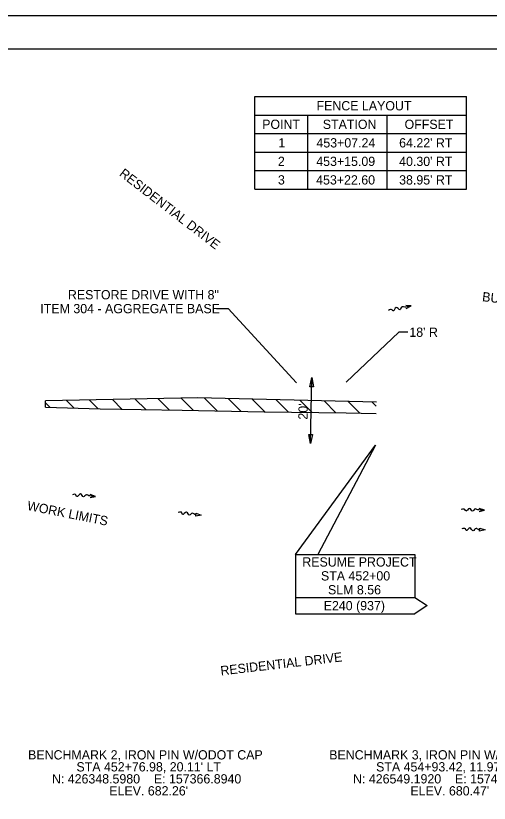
# Model space of a CAD drawing. Extents: x 0 to 3369, y -440 to 440.
# Drawn here: x 196.9 to 340, y 202 to 440 of the extents above; entities that cross this region are included whole.
import ezdxf

# ---------------------------------------------------------------- set-up
doc = ezdxf.new("R2010")
doc.units = 0
for name, color, linetype in [('_CIVIL_CONSTRUCTION', 7, 'Continuous'), ('GE_P_Alignment_100_Distances', 7, 'Continuous'), ('MT_P_PCB', 7, 'Continuous'), ('MT_P_Work_Area', 7, 'Continuous'), ('PF_X_Ground_Line', 7, 'Continuous'), ('PV_P_EOP', 7, 'Continuous'), ('PV_P_Shoulder', 7, 'Continuous'), ('SC_Scratch1', 7, 'Continuous')]:
    doc.layers.add(name, color=color, linetype=linetype)

msp = doc.modelspace()

# ---------------------------------------------------------------- linework, layer by layer
at = {"layer": '_CIVIL_CONSTRUCTION'}
for points in [[(286.92, 327.87), (285.8, 327.9), (286.42, 330.69)], [(285.46, 313.5), (286.58, 313.48), (285.95, 310.69)]]:
    msp.add_lwpolyline(points, close=True, dxfattribs=at)
at = {"layer": 'GE_P_Alignment_100_Distances'}
for p, q in [((251.92, 324.5), (205.89, 323.59)), ((212.23, 323.72), (214.47, 321.47)), ((219.16, 323.85), (221.74, 321.27)), ((226.1, 323.99), (228.96, 321.12)), ((233.03, 324.13), (236.18, 320.98)), ((239.96, 324.26), (243.39, 320.84)), ((246.9, 324.4), (250.6, 320.7)), ((305.91, 323.22), (251.92, 324.5)), ((253.92, 324.45), (257.78, 320.59)), ((261.16, 324.28), (264.97, 320.47)), ((268.4, 324.11), (272.16, 320.35)), ((275.65, 323.94), (279.34, 320.25)), ((282.89, 323.77), (286.51, 320.15)), ((205.84, 321.71), (205.89, 323.59)), ((205.87, 323), (207.2, 321.67)), ((290.13, 323.6), (293.68, 320.04)), ((297.37, 323.42), (300.9, 319.9)), ((304.62, 323.25), (305.88, 321.99))]:
    msp.add_line(p, q, dxfattribs=at)
msp.add_lwpolyline([(205.84, 321.71), (222.36, 321.26), (247.15, 320.76), (272.03, 320.35), (296.81, 320), (305.82, 319.78)], dxfattribs=at)
at = {"layer": 'MT_P_Work_Area'}
for p, q in [((316.44, 352.3), (314.78, 352.41)), ((314.95, 351.57), (316.44, 352.3)), ((220.98, 294.77), (219.41, 295.32)), ((219.35, 294.46), (220.98, 294.77)), ((336.99, 290.22), (338.6, 290.61)), ((338.6, 290.61), (337.01, 291.08))]:
    msp.add_line(p, q, dxfattribs=at)
for points in [[(316.44, 352.3), (314.8, 351.98), (314.13, 352), (313.69, 352.07), (313, 351.18), (311.89, 351.8), (310.95, 350.78), (310.64, 351.17), (309.57, 350.95)], [(220.98, 294.77), (219.32, 294.9), (218.68, 295.09), (218.27, 295.27), (217.37, 294.59), (216.46, 295.49), (215.29, 294.74), (215.09, 295.21), (214, 295.27)], [(338.6, 290.61), (336.94, 290.66), (336.29, 290.82), (335.87, 290.98), (335.01, 290.26), (334.06, 291.11), (332.92, 290.31), (332.7, 290.76), (331.6, 290.78)]]:
    msp.add_spline(points, degree=3, dxfattribs=at)
at = {"layer": 'PF_X_Ground_Line'}
msp.add_lwpolyline([(30, 430), (670, 430), (670, 10), (30, 10)], close=True, dxfattribs=at)
at = {"layer": 'PV_P_EOP'}
for p, q in [((269.18, 415.6), (333.18, 415.6)), ((269.18, 387.6), (269.18, 415.6)), ((333.18, 387.6), (333.18, 415.6)), ((269.18, 410), (333.18, 410)), ((285.18, 387.6), (285.18, 410)), ((309.18, 387.6), (309.18, 410)), ((269.18, 404.4), (333.18, 404.4)), ((269.18, 398.8), (333.18, 398.8)), ((269.18, 393.2), (333.18, 393.2)), ((269.18, 387.6), (333.18, 387.6)), ((257.6, 351.5), (261.06, 351.5)), ((261.06, 351.5), (281.73, 329.1)), ((312.73, 344.37), (296.82, 329.23)), ((315.42, 344.37), (312.73, 344.37)), ((285.95, 310.69), (286.42, 330.69)), ((281.51, 277.24), (281.51, 259.24)), ((281.51, 277.24), (317.51, 277.24)), ((317.51, 277.24), (317.51, 264.24)), ((281.51, 264.24), (317.51, 264.24)), ((281.51, 259.24), (317.51, 259.24))]:
    msp.add_line(p, q, dxfattribs=at)
for points in [[(281.51, 277.24), (305.6, 310.23), (288.23, 277.24)], [(317.51, 264.24), (321.32, 261.74), (317.51, 259.24)]]:
    msp.add_lwpolyline(points, dxfattribs=at)
at = {"layer": 'PV_P_Shoulder'}
for p, q in [((251.35, 288.82), (251.45, 289.67)), ((252.98, 289.05), (251.35, 288.82)), ((251.45, 289.67), (252.98, 289.05)), ((337.14, 284.28), (337.18, 285.13)), ((338.76, 284.63), (337.14, 284.28)), ((337.18, 285.13), (338.76, 284.63))]:
    msp.add_line(p, q, dxfattribs=at)
for points in [[(251.4, 289.25), (251.34, 289.25), (250.7, 289.48), (250.3, 289.67), (249.37, 289.05), (248.51, 289.98), (247.3, 289.3), (247.13, 289.77), (246.03, 289.89)], [(337.16, 284.71), (337.1, 284.71), (336.45, 284.89), (336.04, 285.05), (335.16, 284.36), (334.22, 285.22), (333.07, 284.45), (332.86, 284.91), (331.76, 284.94)]]:
    msp.add_spline(points, degree=3, dxfattribs=at)
at = {"layer": 'SC_Scratch1'}
msp.add_lwpolyline([(0, 0), (680, 0), (680, 440), (0, 440)], close=True, dxfattribs=at)

# ---------------------------------------------------------------- texts
at = {"layer": 'MT_P_PCB'}
for s, rotation, p in [('RESIDENTIAL DRIVE', 322.3237, (227.97, 391.86)), ('BULLSKIN', 353.2855, (337.79, 353.77)), ('RESIDENTIAL DRIVE', 6.5865, (258.94, 240.65))]:
    msp.add_text(s, height=2.8, rotation=rotation, dxfattribs=at).set_placement(p)
at = {"layer": 'PV_P_EOP'}
for s, p in [('FENCE LAYOUT', (287.82, 411.4)), ('POINT', (271.39, 405.8)), ('STATION', (289.71, 405.8)), ('OFFSET', (314.44, 405.8)), ('1', (276.27, 400.2)), ('453+07.24', (287.79, 400.2)), ("64.22' RT", (312.8, 400.2)), ('2', (276.14, 394.6)), ('453+15.09', (287.74, 394.6)), ("40.30' RT", (312.8, 394.6)), ('3', (276.15, 389)), ('453+22.60', (287.71, 389)), ("38.95' RT", (312.8, 389)), ('RESTORE DRIVE WITH 8"', (212.65, 354.3)), ('ITEM 304 - AGGREGATE BASE', (204.31, 350.1)), ("18' R", (315.89, 342.97)), ('RESUME PROJECT', (283.52, 273.54)), ('STA 452+00', (289.16, 269.34)), ('SLM 8.56', (291.29, 265.14)), ('E240 (937)', (289.99, 260.34)), ('BENCHMARK 2, IRON PIN W/ODOT CAP', (200.61, 215.25)), ('BENCHMARK 3, IRON PIN W/ODOT CAP', (291.65, 215.25)), ("STA 452+76.98, 20.11' LT", (215.23, 211.63)), ("STA 454+93.42, 11.97' RT", (305.83, 211.63)), ('N: 426348.5980    E: 157366.8940', (207.82, 208)), ('N: 426549.1920    E: 157452.9500', (298.86, 208)), ("ELEV. 682.26'", (225.16, 204.38)), ("ELEV. 680.47'", (316.2, 204.38))]:
    msp.add_text(s, height=2.8, dxfattribs=at).set_placement(p)
for s, rotation, p in [("20'", 88.6429, (285.08, 317.91)), ('WORK LIMITS', 348.7585, (200.17, 290.69))]:
    msp.add_text(s, height=2.8, rotation=rotation, dxfattribs=at).set_placement(p)

doc.saveas('drawing.dxf')
